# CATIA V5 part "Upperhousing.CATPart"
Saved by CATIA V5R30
Part number: Upperhousing
Bounding box of the stored display mesh (mm): x -40 to 40, y -139 to 75, z 0 to 100
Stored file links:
  D:\CADCIM\CATIA\2020\Ch12\c12_catia_v5_6r2019_tut\c12Tut1\Upperhousing.CATPart
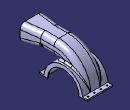
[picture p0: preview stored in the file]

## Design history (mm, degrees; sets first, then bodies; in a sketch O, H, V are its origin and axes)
Set1 "Open_body.1"
  Plane1: type Offset, RefPlane face of Rib1, Offset 57.5, reversed
  Plane2: type Normal, Curve Sketch3, RefPoint Sketch3.P4, Ratio 0
Body1 (main body)
  Sketch1 on yz-plane, origin (0, 0, 0), H (0, 1, 0), V (0, 0, 1)
    arc A1 centre (0, 0) radius 60 from (60, 0) to (-60, 0) ccw
    line L1 (-60, 0) -> (60, 0)
    point P1 (-60, 0)
    radius A1 = 60
    coincidence: P1 H
    horizontal: L1 H
  Pad1: profile Sketch1, direction (1, 0, 0), length 40, mirrored extent
  Sketch2 on Plane2, origin (0, -81.5, -81.5), H (1, 0, 0), V (0, 0, 1)
    line L1 (-28.75, 139.5) -> (28.75, 139.5)
    line L2 (28.75, 139.5) -> (28.75, 181.5)
    line L3 (28.75, 181.5) -> (-28.75, 181.5)
    line L4 (-28.75, 181.5) -> (-28.75, 139.5)
    reference projected point E1 (0, 181.5) from Sketch3.P4
    length L1 = 57.5
    distance L2 V = 28.75
    distance L3 L1 = 42
    horizontal: L1 H, L3 H
    vertical: L2 V, L4 V
    coincidence: L3 E1
  Sketch3 on yz-plane, origin (0, 0, 0), H (0, 1, 0), V (0, 0, 1)
    arc A1 centre (-40, 0) radius 100 from (60, 0) to (-40, 100) ccw
    point P1 (-40, 0)
    point P2 (60, 0)
    line L1 (-81.5, 100) -> (-40, 100)
    point P4 (-81.5, 100)
    point P5 (60, 0)
    radius A1 = 100
    distance P4 V = 81.5
    coincidence: P2 H, P1 H, P5 P2
    horizontal: L1 H
    tangency: L1 A1
  Rib1: profile Sketch2, centre curve Sketch3
  Loft1: solid, Sections (Sketch7; Sketch8)
  Fillet1: radius 45, on edge [face of Rib1 | face of Loft1]
  Fillet2: radius 15, on edge [face of Rib1 | face of Rib1] (x4); edge [face of Loft1 | face of Loft1] (x2); edge [face of Loft1 | face of Rib1]; edge [face of Rib1 | face of Loft1]
  Fillet3: radius 5, on edge [face of Rib1 | face of Pad1 from Sketch1.A1]
  Shell1: ExtOffset 0, Face (face; face), IntOffset 2.5
  Sketch4 on face of Pad1, origin (40, 0, 0), H (0, 1, 0), V (0, 0, 1)
    circle A1 centre (0, 0) radius 49
    circle A2 centre (0, 0) radius 15
    radius A1 = 49
    radius A2 = 15
  MultiPocket1: profile Sketch4, domains (length 203.2; length 25.4)
  Sketch5 on xy-plane, origin (0, 0, 0), H (1, 0, 0), V (0, 1, 0)
    line L1 (40, 75) -> (-40, 75)
    line L2 (-40, 75) -> (-40, 57.5)
    line L3 (-40, 57.5) -> (40, 57.5)
    line L4 (40, 57.5) -> (40, 75)
    reference projected line E1 (40, 60) -> (40, -60) from edge [face of Pad1 from Sketch1.A1 | end face of Pad1]
    reference projected line E2 (-40, 60) -> (-40, -60) from edge [start face of Pad1 | face of Pad1 from Sketch1.A1]
    reference projected line E3 (-13.75, 57.5) -> (13.75, 57.5) from edge [face of Rib1 | face of Shell1]
    distance L1 H = 75
    horizontal: L1 H, L3 H
    vertical: L2 V, L4 V
    coincidence: L4 E1, L2 E2, L3 E3
  Pad2: profile Sketch5, direction (0, 0, 1), length 4
  Mirror1: of Pad2, Sketch5, about zx-plane
  Sketch6 on face of Pad2, origin (0, 0, 4), H (1, 0, 0), V (0, 1, 0)
    circle A1 centre (30, 67.5) radius 2
    point P1 (30, 67.5)
    reference projected line E1 (40, 75) -> (-40, 75) from edge [face of Pad2 from Sketch5.L1 | end face of Pad2]
    reference projected line E2 (40, 57.5) -> (40, 75) from edge [face of Pad2 from Sketch5.L4 | end face of Pad2]
    radius A1 = 2
    distance P1 E1 = 7.5
    distance P1 E2 = 10
  Pocket1: profile Sketch6, direction (0, 0, -1), through (limit type 6)
  RectPattern1: of Pocket1, direction 1 instances 4, spacing 20, along edge of Pad2 reversed, direction 2 instances 2, spacing 135, along edge of Pad1
  Sketch7 on face of Rib1, origin (0, -81.5, 0), H (1, 0, 0), V (0, 0, 1)
  Sketch8 on Plane1, origin (0, -139, 0), H (-1, 0, 0), V (0, 0, 1)
    line L1 (36.25, 100) -> (-36.25, 100)
    line L2 (-36.25, 100) -> (-36.25, 47.5)
    line L3 (-36.25, 47.5) -> (36.25, 47.5)
    line L4 (36.25, 47.5) -> (36.25, 100)
    reference projected line E1 (-28.75, 100) -> (28.75, 100) from Sketch2.L3
    length L2 = 52.5
    length L1 = 72.5
    distance V L2 = 36.25
    horizontal: L1 H, L3 H
    vertical: L2 V, L4 V
    coincidence: L1 E1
